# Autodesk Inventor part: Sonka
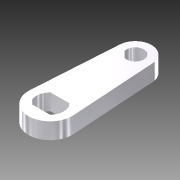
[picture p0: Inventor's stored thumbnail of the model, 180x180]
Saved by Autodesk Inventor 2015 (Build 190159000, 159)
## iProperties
Created: 2013-02
Part Number: Sonka
Material: Generic
Document SubType Name: Modeling
Designer: Marci
Density: 1 g/cm^3
Mass: 46.6344 g
Surface Area: 120.894 cm^2
Volume: 46.6344 cm^3
Appearance: Aluminum - Polished
Author: Marci
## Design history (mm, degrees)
sketch "Sketch1"
  geometry: L1 (136.285, 8.645)-(141.275, 86.324); L2 (176.203, 8.645)-(171.213, 86.324); L3 (156.244, 16.363)-(147.569, 16.363); L4 (156.244, 16.363)-(164.919, 16.363); L5 (156.244, -1.637)-(147.569, -1.637); L6 (156.244, -1.637)-(164.919, -1.637); C1 r 8 at (156.244, 85.363); A1 r 15 centre (156.244, 85.363) between (171.213, 86.324) and (141.275, 86.324); A2 r 20 centre (156.244, 7.363) between (136.285, 8.645) and (176.203, 8.645); A3 r 12.5 centre (156.244, 7.363) between (147.569, 16.363) and (147.569, -1.637); A4 r 12.5 centre (156.244, 7.363) between (164.919, -1.637) and (164.919, 16.363)
  constraints: 12 end point, 8 point on circle, 5 centre point, 2 coincident, 2 tangent, 1 collinear
  dimensions: "d9" = 30 diameter of A1; "d10" = 40 diameter of A2; "d13" = 16 diameter of C1
extrude "Extrusion1" new body sketch "Sketch1" distance "d14" = 15; taper "d15" = 0 deg
body "Solid1"
other parameters: "d11" = 25
